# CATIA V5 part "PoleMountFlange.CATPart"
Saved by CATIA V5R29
Part number: PoleMountFlange
Source: Unknown
Bounding box of the stored display mesh (mm): x -44 to 44, y -44 to 44, z -30 to 0
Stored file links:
  C:\가치같이\SmartFactory_BoxErectorConveyor\Boxing(under)\PoleMountFlange.CATPart
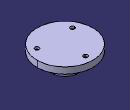
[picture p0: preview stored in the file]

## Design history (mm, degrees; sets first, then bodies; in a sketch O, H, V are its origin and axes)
Body1 (main body)
  Solid1 "PartBody": solid without history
